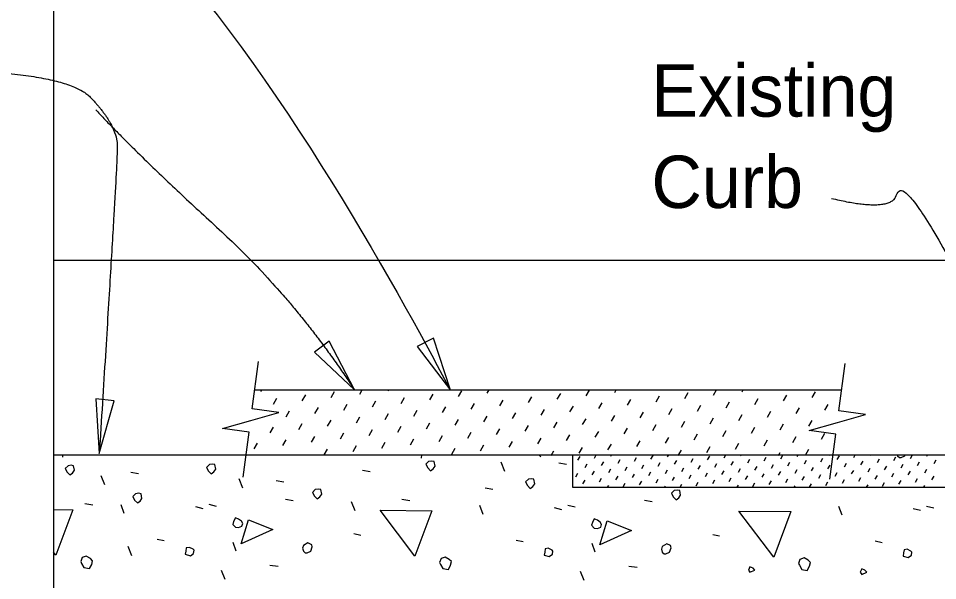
# Model space of a CAD drawing. Extents: x 1.5 to 68.7, y 0 to 31.
# Drawn here: x 25.337 to 28.879, y 11.448 to 13.614 of the extents above; entities that cross this region are included whole.
import ezdxf

# ---------------------------------------------------------------- set-up
doc = ezdxf.new("R2010")
doc.units = 0
for name, color, linetype in [('AdhocPoint_dp', 7, 'Continuous'), ('Patterning', 7, 'Continuous'), ('PlotBorder_dp', 7, 'Continuous')]:
    doc.layers.add(name, color=color, linetype=linetype)

msp = doc.modelspace()

# ---------------------------------------------------------------- linework, layer by layer
at = {"layer": 'AdhocPoint_dp'}
for points in [[(26.6316, 12.1828), (26.5349, 12.3706), (26.4784, 12.3283)], [(27.0016, 12.1811), (26.9365, 12.3821), (26.8739, 12.3494)], [(25.6483, 11.937), (25.7052, 12.1404), (25.635, 12.1478)]]:
    msp.add_lwpolyline(points, close=True, dxfattribs=at)
for points in [[(26.2031, 11.8459), (26.2263, 12.0198), (26.1238, 12.0334), (26.2322, 12.0644), (26.3406, 12.0953), (26.2382, 12.109), (26.2625, 12.2913)], [(28.4639, 11.8386), (28.4871, 12.0124), (28.3846, 12.0261), (28.493, 12.057), (28.6014, 12.0879), (28.499, 12.1016), (28.5233, 12.284)]]:
    msp.add_lwpolyline(points, dxfattribs=at)
for points, degree in [([(24.5331, 14.4952), (24.8538, 14.4726), (25.7837, 14.4447), (26.8575, 12.4571), (27.0016, 12.1811)], 3), ([(24.8609, 13.4204), (25.5071, 13.4204), (25.7178, 13.2026), (25.7178, 13.041), (25.6483, 11.9369)], 2), ([(25.635, 13.2612), (25.8091, 13.0761), (26.4025, 12.5334), (26.6316, 12.1828)], 2), ([(28.4708, 12.9203), (28.7034, 12.864), (28.7449, 13.0099), (29.089, 12.3912), (29.2714, 12.2154)], 2)]:
    msp.add_open_spline(points, degree=degree, dxfattribs=at)
at = {"layer": 'Patterning'}
for p, q in [((26.2715, 12.1764), (26.2747, 12.182)), ((26.431, 12.1405), (26.4439, 12.1629)), ((26.5416, 12.1535), (26.5546, 12.1759)), ((26.6522, 12.1665), (26.6612, 12.182)), ((26.7629, 12.1794), (26.7643, 12.182)), ((26.8117, 12.1306), (26.8247, 12.153)), ((26.9223, 12.1435), (26.9353, 12.1659)), ((27.033, 12.1565), (27.0459, 12.1789)), ((27.1436, 12.1695), (27.1508, 12.182)), ((27.3031, 12.1336), (27.316, 12.156)), ((27.4137, 12.1466), (27.4267, 12.169)), ((27.5243, 12.1595), (27.5373, 12.1819)), ((27.635, 12.1725), (27.6405, 12.182)), ((27.7944, 12.1366), (27.8074, 12.159)), ((27.9051, 12.1496), (27.918, 12.172)), ((28.0157, 12.1625), (28.0269, 12.182)), ((28.1263, 12.1755), (28.1301, 12.182)), ((28.2858, 12.1396), (28.2988, 12.162)), ((28.3964, 12.1526), (28.4094, 12.175)), ((26.3203, 12.1276), (26.3333, 12.15)), ((26.5904, 12.1047), (26.6034, 12.127)), ((26.7011, 12.1176), (26.714, 12.14)), ((26.9712, 12.0947), (26.9841, 12.1171)), ((27.0818, 12.1077), (27.0948, 12.1301)), ((27.1924, 12.1206), (27.2054, 12.143)), ((27.4625, 12.0977), (27.4755, 12.1201)), ((27.5732, 12.1107), (27.5861, 12.1331)), ((27.6838, 12.1237), (27.6968, 12.146)), ((27.9539, 12.1008), (27.9669, 12.1231)), ((28.0645, 12.1137), (28.0775, 12.1361)), ((28.1752, 12.1267), (28.1881, 12.1491)), ((28.4453, 12.1038), (28.4582, 12.1262)), ((26.3692, 12.0787), (26.3821, 12.1011)), ((26.4798, 12.0917), (26.4928, 12.1141)), ((26.7499, 12.0688), (26.7629, 12.0912)), ((26.8605, 12.0817), (26.8735, 12.1041)), ((27.1306, 12.0588), (27.1436, 12.0812)), ((27.2413, 12.0718), (27.2542, 12.0942)), ((27.3519, 12.0848), (27.3649, 12.1072)), ((27.622, 12.0619), (27.635, 12.0843)), ((27.7326, 12.0748), (27.7456, 12.0972)), ((27.8433, 12.0878), (27.8562, 12.1102)), ((28.1134, 12.0649), (28.1263, 12.0873)), ((28.224, 12.0778), (28.237, 12.1002)), ((28.3346, 12.0908), (28.3476, 12.1132)), ((26.418, 12.0299), (26.431, 12.0523)), ((26.5286, 12.0429), (26.5416, 12.0652)), ((26.6393, 12.0558), (26.6522, 12.0782)), ((26.9094, 12.0329), (26.9223, 12.0553)), ((27.02, 12.0459), (27.033, 12.0683)), ((27.4007, 12.0359), (27.4137, 12.0583)), ((27.5114, 12.0489), (27.5243, 12.0713)), ((27.7815, 12.026), (27.7944, 12.0484)), ((27.8921, 12.039), (27.9051, 12.0613)), ((28.0027, 12.0519), (28.0157, 12.0743)), ((28.2728, 12.029), (28.2858, 12.0514)), ((28.3835, 12.042), (28.3964, 12.0644)), ((26.3074, 12.0169), (26.3203, 12.0393)), ((26.5775, 11.994), (26.5904, 12.0164)), ((26.6881, 12.007), (26.7011, 12.0294)), ((26.7987, 12.0199), (26.8117, 12.0423)), ((27.0688, 11.997), (27.0818, 12.0194)), ((27.1795, 12.01), (27.1924, 12.0324)), ((27.2901, 12.023), (27.3031, 12.0454)), ((27.5602, 12.0001), (27.5732, 12.0225)), ((27.6708, 12.013), (27.6838, 12.0354)), ((27.9409, 11.9901), (27.9539, 12.0125)), ((28.0516, 12.0031), (28.0645, 12.0255)), ((28.1622, 12.016), (28.1752, 12.0384)), ((28.4323, 11.9931), (28.4453, 12.0155)), ((26.2456, 11.9551), (26.2585, 11.9775)), ((26.3562, 11.9681), (26.3692, 11.9905)), ((26.4668, 11.9811), (26.4798, 12.0034)), ((26.7369, 11.9582), (26.7499, 11.9805)), ((26.8476, 11.9711), (26.8605, 11.9935)), ((26.9582, 11.9841), (26.9712, 12.0065)), ((27.2283, 11.9612), (27.2413, 11.9836)), ((27.3389, 11.9741), (27.3519, 11.9965)), ((27.4496, 11.9871), (27.4625, 12.0095)), ((27.7197, 11.9642), (27.7326, 11.9866)), ((27.8303, 11.9772), (27.8433, 11.9995)), ((28.1004, 11.9542), (28.1134, 11.9766)), ((28.211, 11.9672), (28.224, 11.9896)), ((28.3217, 11.9802), (28.3346, 12.0026)), ((26.5157, 11.9322), (26.5286, 11.9546)), ((26.6263, 11.9452), (26.6393, 11.9676)), ((27.007, 11.9352), (27.02, 11.9576)), ((27.1177, 11.9482), (27.1306, 11.9706)), ((27.39, 11.9291), (27.4007, 11.9477)), ((27.4984, 11.9383), (27.5114, 11.9607)), ((27.609, 11.9512), (27.622, 11.9736)), ((27.8796, 11.9291), (27.8921, 11.9507)), ((27.9898, 11.9413), (28.0027, 11.9637)), ((28.2661, 11.9291), (28.2728, 11.9408)), ((28.3705, 11.9313), (28.3835, 11.9537)), ((27.4931, 11.9111), (27.5012, 11.9251)), ((27.5566, 11.9192), (27.564, 11.932)), ((27.5843, 11.8915), (27.5924, 11.9055)), ((27.6201, 11.9273), (27.6228, 11.932)), ((27.6477, 11.8996), (27.6558, 11.9136)), ((27.7112, 11.9077), (27.7193, 11.9217)), ((27.7747, 11.9158), (27.7828, 11.9298)), ((27.8382, 11.9239), (27.8429, 11.932)), ((27.8659, 11.8962), (27.874, 11.9102)), ((27.9294, 11.9043), (27.9375, 11.9183)), ((27.9929, 11.9124), (28.001, 11.9264)), ((28.0564, 11.9205), (28.063, 11.932)), ((28.0841, 11.8928), (28.0922, 11.9068)), ((28.1199, 11.9286), (28.1218, 11.932)), ((28.1476, 11.9009), (28.1557, 11.9149)), ((28.2111, 11.909), (28.2192, 11.923)), ((28.2746, 11.9171), (28.2827, 11.9311)), ((28.3381, 11.9252), (28.342, 11.932)), ((28.3658, 11.8976), (28.3739, 11.9115)), ((28.4292, 11.9057), (28.4373, 11.9196)), ((28.4671, 11.9285), (28.4658, 11.932)), ((28.4927, 11.9138), (28.5008, 11.9278)), ((28.5562, 11.9219), (28.5621, 11.932)), ((28.5839, 11.8942), (28.592, 11.9082)), ((28.6197, 11.93), (28.6209, 11.932)), ((28.6474, 11.9023), (28.6555, 11.9163)), ((28.7109, 11.9104), (28.719, 11.9244)), ((28.7744, 11.9185), (28.7822, 11.932)), ((28.8021, 11.8908), (28.8102, 11.9048)), ((28.8379, 11.9266), (28.841, 11.932)), ((28.8656, 11.8989), (28.8737, 11.9129)), ((26.6626, 11.8732), (26.6926, 11.8679)), ((27.2115, 11.8681), (27.1974, 11.9034)), ((27.4195, 11.9013), (27.4495, 11.896)), ((27.5208, 11.8834), (27.5289, 11.8974)), ((27.5485, 11.8557), (27.5566, 11.8697)), ((27.6119, 11.8638), (27.6201, 11.8778)), ((27.6754, 11.8719), (27.6835, 11.8859)), ((27.7389, 11.88), (27.747, 11.894)), ((27.8024, 11.8881), (27.8105, 11.9021)), ((27.8301, 11.8604), (27.8382, 11.8744)), ((27.8936, 11.8685), (27.9017, 11.8825)), ((27.9571, 11.8766), (27.9652, 11.8906)), ((28.0206, 11.8847), (28.0287, 11.8987)), ((28.0483, 11.857), (28.0564, 11.871)), ((28.1118, 11.8651), (28.1199, 11.8791)), ((28.1753, 11.8732), (28.1834, 11.8872)), ((28.2388, 11.8813), (28.2469, 11.8953)), ((28.3023, 11.8894), (28.3104, 11.9034)), ((28.33, 11.8618), (28.3381, 11.8757)), ((28.3934, 11.8699), (28.4016, 11.8839)), ((28.4569, 11.878), (28.465, 11.892)), ((28.5204, 11.8861), (28.5285, 11.9001)), ((28.5481, 11.8584), (28.5562, 11.8724)), ((28.6116, 11.8665), (28.6197, 11.8805)), ((28.6751, 11.8746), (28.6832, 11.8886)), ((28.7386, 11.8827), (28.7467, 11.8967)), ((28.7663, 11.855), (28.7744, 11.869)), ((28.8298, 11.8631), (28.8379, 11.8771)), ((25.6696, 11.816), (25.6555, 11.8513)), ((25.7695, 11.8652), (25.7995, 11.8599)), ((26.2023, 11.8039), (26.1881, 11.8393)), ((26.3301, 11.8332), (26.3602, 11.8279)), ((27.485, 11.8476), (27.4931, 11.8616)), ((27.5127, 11.8199), (27.5208, 11.8339)), ((27.5762, 11.828), (27.5843, 11.842)), ((27.6396, 11.8361), (27.6477, 11.8501)), ((27.7031, 11.8442), (27.7112, 11.8582)), ((27.7666, 11.8523), (27.7747, 11.8663)), ((27.7943, 11.8246), (27.8024, 11.8386)), ((27.8578, 11.8327), (27.8659, 11.8467)), ((27.9213, 11.8408), (27.9294, 11.8548)), ((27.9848, 11.8489), (27.9929, 11.8629)), ((28.0125, 11.8212), (28.0206, 11.8352)), ((28.076, 11.8293), (28.0841, 11.8433)), ((28.1395, 11.8374), (28.1476, 11.8514)), ((28.203, 11.8456), (28.2111, 11.8595)), ((28.2665, 11.8537), (28.2746, 11.8676)), ((28.2942, 11.826), (28.3023, 11.84)), ((28.3577, 11.8341), (28.3658, 11.8481)), ((28.4211, 11.8422), (28.4292, 11.8562)), ((28.4846, 11.8503), (28.4927, 11.8643)), ((28.5123, 11.8226), (28.5204, 11.8366)), ((28.5758, 11.8307), (28.5839, 11.8447)), ((28.6393, 11.8388), (28.6474, 11.8528)), ((28.7028, 11.8469), (28.7109, 11.8609)), ((28.7305, 11.8192), (28.7386, 11.8332)), ((28.794, 11.8273), (28.8021, 11.8413)), ((28.8575, 11.8354), (28.8656, 11.8494)), ((27.1351, 11.8051), (27.1652, 11.7998)), ((27.6077, 11.807), (27.6119, 11.8143)), ((27.6673, 11.8084), (27.6754, 11.8224)), ((27.7308, 11.8165), (27.7389, 11.8305)), ((27.8278, 11.807), (27.8301, 11.8109)), ((27.8866, 11.807), (27.8936, 11.819)), ((27.949, 11.8131), (27.9571, 11.8271)), ((28.048, 11.807), (28.0483, 11.8075)), ((28.1068, 11.807), (28.1118, 11.8156)), ((28.1672, 11.8098), (28.1753, 11.8237)), ((28.2307, 11.8179), (28.2388, 11.8319)), ((28.3269, 11.807), (28.33, 11.8123)), ((28.3857, 11.807), (28.3934, 11.8204)), ((28.4488, 11.8145), (28.4569, 11.8285)), ((28.547, 11.807), (28.5481, 11.8089)), ((28.6058, 11.807), (28.6116, 11.817)), ((28.667, 11.8111), (28.6751, 11.8251)), ((28.826, 11.807), (28.8298, 11.8136)), ((25.5932, 11.745), (25.6233, 11.7397)), ((25.7448, 11.7062), (25.7324, 11.7398)), ((26.0188, 11.7327), (26.0471, 11.7257)), ((26.0705, 11.742), (26.0988, 11.7349)), ((26.3662, 11.761), (26.3962, 11.7557)), ((26.6348, 11.7158), (26.6206, 11.7511)), ((26.8147, 11.761), (26.8448, 11.7557)), ((27.1281, 11.7027), (27.1157, 11.7363)), ((27.4021, 11.7292), (27.4304, 11.7221)), ((27.4538, 11.7385), (27.4821, 11.7314)), ((27.7495, 11.7575), (27.7795, 11.7522)), ((28.5114, 11.6991), (28.499, 11.7327)), ((28.8371, 11.7349), (28.8654, 11.7279)), ((28.7854, 11.7257), (28.8137, 11.7186)), ((26.6296, 11.6284), (26.6561, 11.6231)), ((28.0129, 11.6249), (28.0394, 11.6196)), ((25.8721, 11.6072), (25.8986, 11.6019)), ((26.1766, 11.5608), (26.1642, 11.5944)), ((27.2554, 11.6037), (27.2819, 11.5984)), ((27.5599, 11.5573), (27.5475, 11.5909)), ((28.6387, 11.6002), (28.6652, 11.5948)), ((25.7737, 11.5434), (25.7596, 11.5788)), ((26.1342, 11.4512), (26.12, 11.4866)), ((26.3061, 11.5065), (26.3379, 11.5029)), ((27.5174, 11.4477), (27.5033, 11.483)), ((27.6894, 11.5029), (27.7212, 11.4994))]:
    msp.add_line(p, q, dxfattribs=at)
for points in [[(25.5073, 11.932), (25.5061, 11.9232)], [(26.8902, 11.932), (26.8885, 11.9197)], [(26.9141, 11.8816), (26.9247, 11.871), (26.9353, 11.8781), (26.9424, 11.8887), (26.9388, 11.9064), (26.93, 11.9081), (26.9176, 11.9064), (26.907, 11.8958), (26.9141, 11.8816)], [(27.3429, 11.932), (27.3499, 11.925)], [(28.724, 11.932), (28.7252, 11.9285), (28.7323, 11.9215)], [(28.7323, 11.9215), (28.7393, 11.9215), (28.7535, 11.9285), (28.7546, 11.932)], [(25.5244, 11.8656), (25.535, 11.855), (25.5456, 11.862), (25.5527, 11.8727), (25.5491, 11.8903), (25.5403, 11.8921), (25.5279, 11.8903), (25.5173, 11.8797), (25.5244, 11.8656)], [(26.0691, 11.8696), (26.0797, 11.859), (26.0903, 11.8661), (26.0973, 11.8767), (26.0938, 11.8943), (26.085, 11.8961), (26.0726, 11.8943), (26.062, 11.8837), (26.0691, 11.8696)], [(27.2986, 11.8135), (27.3092, 11.8029), (27.3198, 11.8099), (27.3269, 11.8205), (27.3233, 11.8382), (27.3145, 11.84), (27.3021, 11.8382), (27.2915, 11.8276), (27.2986, 11.8135)], [(26.4776, 11.7734), (26.4882, 11.7628), (26.4988, 11.7699), (26.5058, 11.7805), (26.5023, 11.7981), (26.4935, 11.7999), (26.4811, 11.7981), (26.4705, 11.7875), (26.4776, 11.7734)], [(25.7847, 11.7574), (25.7953, 11.7468), (25.8059, 11.7538), (25.813, 11.7644), (25.8095, 11.7821), (25.8006, 11.7839), (25.7882, 11.7821), (25.7776, 11.7715), (25.7847, 11.7574)], [(27.8608, 11.7699), (27.8714, 11.7593), (27.8821, 11.7663), (27.8891, 11.7769), (27.8856, 11.7946), (27.8767, 11.7964), (27.8644, 11.7946), (27.8538, 11.784), (27.8608, 11.7699)], [(25.4726, 11.721), (25.5468, 11.7204), (25.4814, 11.5454)], [(26.8647, 11.5418), (26.7304, 11.7186), (26.9301, 11.7168), (26.8647, 11.5418)], [(28.248, 11.5383), (28.1136, 11.7151), (28.3134, 11.7133), (28.248, 11.5383)], [(26.1731, 11.6536), (26.1854, 11.6519), (26.1978, 11.6572), (26.2013, 11.6678), (26.196, 11.6766), (26.1854, 11.6837), (26.1731, 11.689), (26.166, 11.6748), (26.1625, 11.6642), (26.1731, 11.6536)], [(26.1947, 11.5895), (26.223, 11.6815), (26.3167, 11.6443), (26.1947, 11.5895)], [(27.5563, 11.6501), (27.5687, 11.6483), (27.5811, 11.6536), (27.5846, 11.6642), (27.5793, 11.6731), (27.5687, 11.6801), (27.5563, 11.6854), (27.5493, 11.6713), (27.5457, 11.6607), (27.5563, 11.6501)], [(27.578, 11.586), (27.6063, 11.6779), (27.7, 11.6408), (27.578, 11.586)], [(26.4422, 11.5542), (26.4493, 11.5542), (26.4634, 11.5613), (26.4687, 11.5772), (26.467, 11.586), (26.4528, 11.5931), (26.4351, 11.5825), (26.4316, 11.5719), (26.4351, 11.5613), (26.4422, 11.5542)], [(27.8255, 11.5507), (27.8326, 11.5507), (27.8467, 11.5577), (27.852, 11.5736), (27.8502, 11.5825), (27.8361, 11.5895), (27.8184, 11.5789), (27.8149, 11.5683), (27.8184, 11.5577), (27.8255, 11.5507)], [(25.4814, 11.5454), (25.4726, 11.557)], [(25.9799, 11.5489), (25.9994, 11.5436), (26.0118, 11.5524), (26.0135, 11.5648), (26.01, 11.5683), (25.9958, 11.5754), (25.9835, 11.5736), (25.9817, 11.5613), (25.9799, 11.5489)], [(27.3632, 11.5454), (27.3827, 11.54), (27.395, 11.5489), (27.3968, 11.5613), (27.3933, 11.5648), (27.3791, 11.5719), (27.3667, 11.5701), (27.365, 11.5577), (27.3632, 11.5454)], [(28.7465, 11.5418), (28.7659, 11.5365), (28.7783, 11.5454), (28.7801, 11.5577), (28.7765, 11.5613), (28.7624, 11.5683), (28.75, 11.5666), (28.7483, 11.5542), (28.7465, 11.5418)], [(25.5804, 11.5135), (25.5893, 11.4976), (25.6105, 11.4941), (25.6193, 11.51), (25.6228, 11.5241), (25.614, 11.533), (25.5981, 11.5418), (25.5822, 11.5365), (25.5769, 11.5206), (25.5804, 11.5135)], [(26.9637, 11.51), (26.9725, 11.4941), (26.9937, 11.4906), (27.0026, 11.5065), (27.0061, 11.5206), (26.9973, 11.5294), (26.9814, 11.5383), (26.9655, 11.533), (26.9602, 11.5171), (26.9637, 11.51)], [(28.347, 11.5065), (28.3558, 11.4906), (28.377, 11.487), (28.3859, 11.5029), (28.3894, 11.5171), (28.3806, 11.5259), (28.3647, 11.5347), (28.3487, 11.5294), (28.3434, 11.5135), (28.347, 11.5065)], [(28.1561, 11.4795), (28.1756, 11.4883), (28.1685, 11.4954), (28.1561, 11.5007), (28.1508, 11.4883), (28.1561, 11.4795)], [(28.5868, 11.4712), (28.6063, 11.4801), (28.5992, 11.4872), (28.5868, 11.4925), (28.5815, 11.4801), (28.5868, 11.4712)]]:
    msp.add_lwpolyline(points, dxfattribs=at)
at = {"layer": 'PlotBorder_dp'}
for p, q in [((25.4726, 14.7653), (25.4726, 12.682)), ((25.4726, 12.682), (25.4726, 10.0773)), ((25.4726, 12.682), (34.6205, 12.682)), ((26.2479, 12.182), (28.5097, 12.182)), ((25.4726, 11.932), (31.1267, 11.932)), ((27.4727, 11.932), (27.4727, 11.807)), ((27.4727, 11.807), (31.0765, 11.807))]:
    msp.add_line(p, q, dxfattribs=at)

# ---------------------------------------------------------------- texts
at = {"layer": 'AdhocPoint_dp'}
for s, p in [('Existing ', (27.7764, 13.2353)), ('Curb', (27.7764, 12.8833))]:
    msp.add_text(s, height=0.2016, dxfattribs=at).set_placement(p)

doc.saveas('drawing.dxf')
